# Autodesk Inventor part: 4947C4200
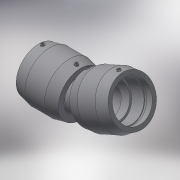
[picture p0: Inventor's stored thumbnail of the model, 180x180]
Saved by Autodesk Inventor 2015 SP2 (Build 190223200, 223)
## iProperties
Created: 2017-06
Part Number: 4947C4200
Material: Generic
Description: PLASSON ADJUSTABLE ELBOW 200
Document SubType Name: Modeling
Designer: KIM
Mass: 8409.77 g
Surface Area: 7869.48 cm^2
Volume: 8409.77 cm^3
Density: 1 g/cm^3
Appearance: Default
Author: KIM
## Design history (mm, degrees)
derived "4947C4.ipt"
feature "Solid1::4947C4.ipt"
tag "TaggingFeature1"
body "Solid1"
other parameters: "d0" = 204.8, "d3" = 104, "d4" = 52, "d5" = 225, "d8" = 168 deg, "d10" = 41.6, "d11" = 13.86667, "d29" = 125, "d30" = 15, "d31" = 81.92, "d34" = 5 deg, "d41" = 4, "d42" = 14, "d43" = 0, "d49" = 24 deg, "d50" = 512, "d51" = 78 deg, "d52" = 90 deg, "d55" = 50.4, "d57" = 168 deg, "d58" = 10.08, "d60" = 60.1776, "d62" = 3, "d63" = 0, "L_" = 512, "L_1" = 104, "A_" = 125, "d_2" = 12, "L_0" = 148, "d54" = 100.8, "d59" = 200.59199
